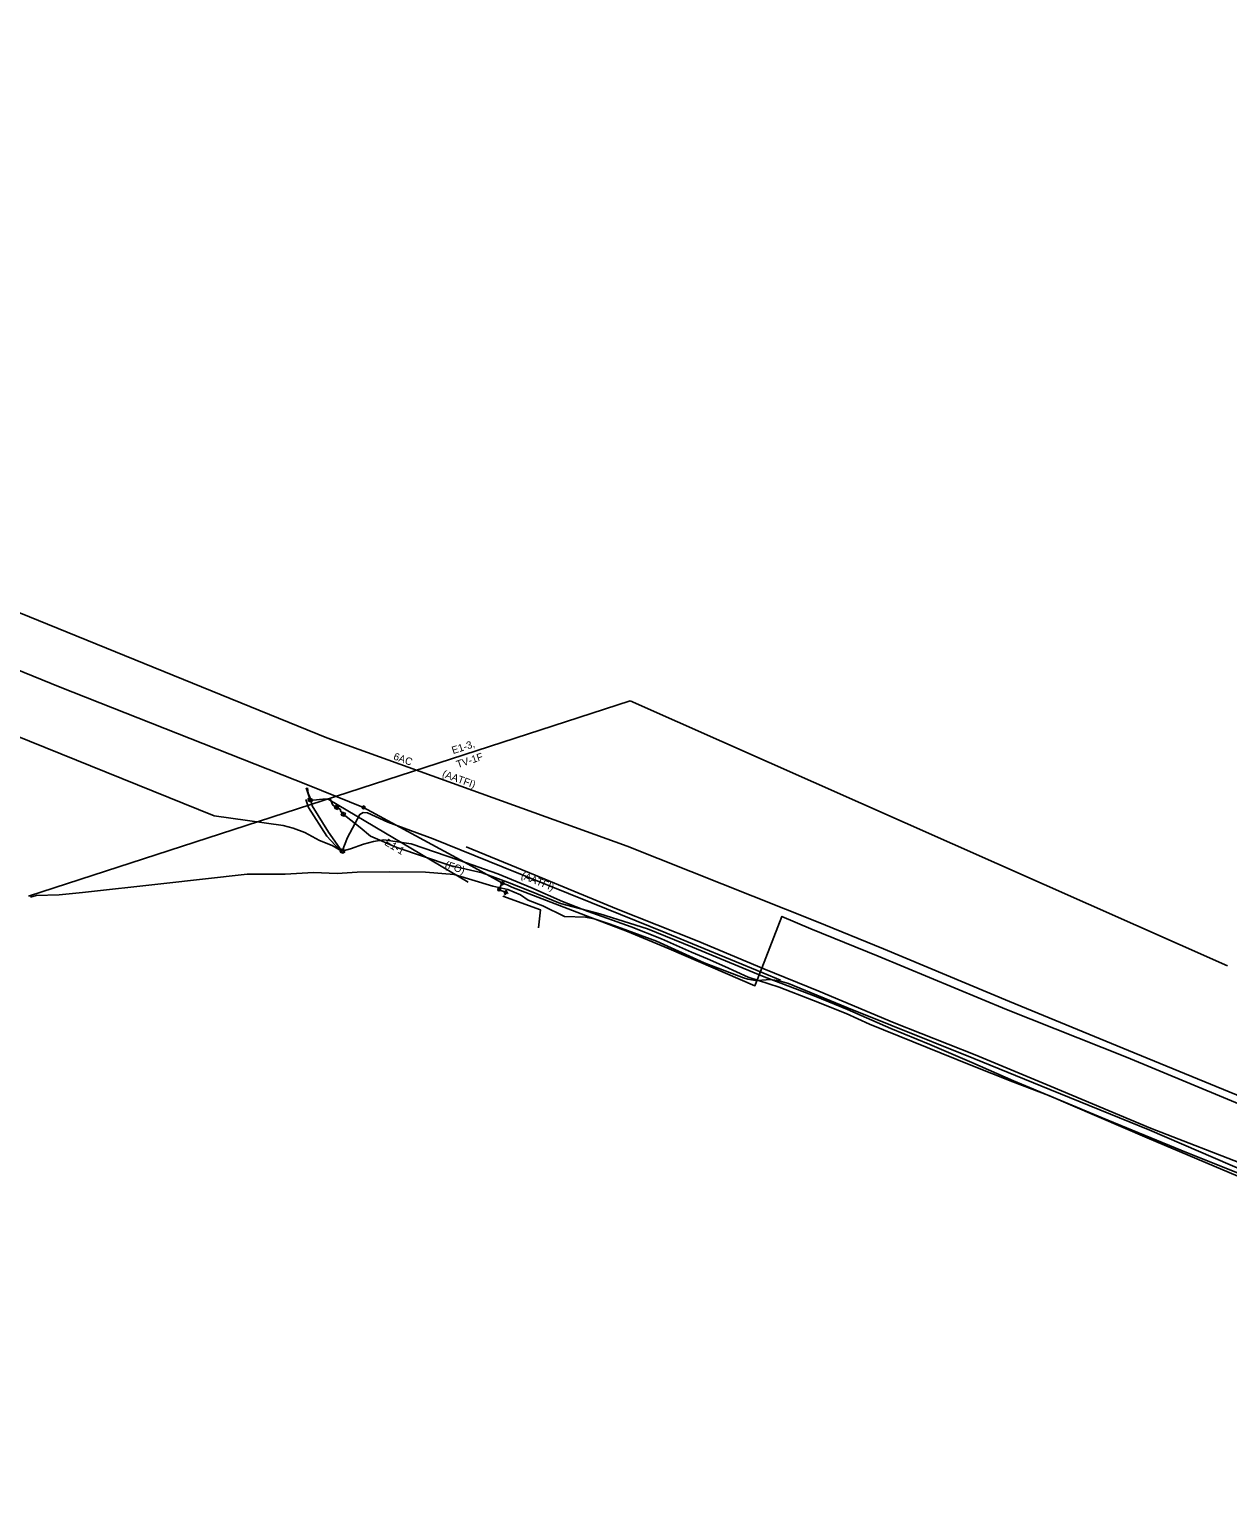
# Model space of a CAD drawing. Extents: x 2166631 to 2170707, y 207428 to 209111.
# Drawn here: x 2169640 to 2170250, y 207433 to 208185 of the extents above; entities that cross this region are included whole.
import ezdxf

# ---------------------------------------------------------------- set-up
doc = ezdxf.new("R2010")
doc.units = 0
for name, color, linetype in [('RD_EX_SU_Elec', 7, 'Continuous'), ('RD_EX_SU_H2O', 7, 'Continuous'), ('RD_EX_SU_Misc', 7, 'Continuous'), ('RD_EX_SU_Ovhd', 7, 'Continuous'), ('RD_EX_SU_Telecom', 7, 'Continuous'), ('RD_EX_SU_TX_H2O', 7, 'Continuous'), ('RD_EX_SU_TX_Ovhd', 7, 'Continuous'), ('RD_EX_SU_TX_Telecom', 7, 'Continuous'), ('RD_EX_UT', 7, 'Continuous')]:
    doc.layers.add(name, color=color, linetype=linetype)

msp = doc.modelspace()

# ---------------------------------------------------------------- linework, layer by layer
at = {"layer": 'RD_EX_SU_Elec'}
for p, q in [((2169782.23, 207792.66), (2169781.54, 207792.94)), ((2169783.6, 207792.1), (2169784.31, 207791.81))]:
    msp.add_line(p, q, dxfattribs=at)
msp.add_lwpolyline([(2169780.98, 207798.51), (2169782.91, 207792.38), (2169784.43, 207792.27), (2169789.41, 207792.82), (2169793.01, 207792.88)], dxfattribs=at)
msp.add_lwpolyline([(2169781.95, 207791.98), (2169783.32, 207791.42), (2169783.88, 207792.78), (2169782.51, 207793.34)], close=True, dxfattribs=at)
at = {"layer": 'RD_EX_SU_H2O'}
for p, q in [((2169882.14, 207744.71), (2169881.95, 207744.22)), ((2169881.95, 207744.22), (2169882.26, 207744.1)), ((2169882.26, 207744.1), (2169882.46, 207744.6)), ((2169882.81, 207746.41), (2169882.62, 207745.93)), ((2169883.12, 207746.28), (2169882.81, 207746.41)), ((2169882.93, 207745.8), (2169883.12, 207746.28)), ((2169883.05, 207744.86), (2169883.45, 207744.7)), ((2169883.58, 207745.01), (2169883.18, 207745.17)), ((2169883.45, 207744.7), (2169883.58, 207745.01))]:
    msp.add_line(p, q, dxfattribs=at)
for points in [[(2167150.83, 208898.91), (2167395.21, 208799.32), (2168738, 208252.12), (2168771.81, 208104.5), (2168930.48, 208039.81), (2169042.32, 208128.69), (2169791.43, 207823.92)], [(2167144.87, 208875.61), (2167820.52, 208600.61), (2168758.4, 208215.02), (2168781.36, 208111.79), (2168927.74, 208052.43), (2169006.44, 208114.13), (2169655.67, 207849.79), (2169781.62, 207799.98)], [(2169791.43, 207823.92), (2169944.38, 207768.79), (2170040.91, 207730.46)], [(2169781.62, 207799.98), (2169810.21, 207788.55), (2169863.45, 207759.58)], [(2169863.45, 207759.58), (2169880.88, 207749.91), (2169883.32, 207749.12), (2169885.67, 207747.99), (2169923.16, 207733.55), (2169944.55, 207725.32), (2169965.76, 207716.47), (2170009.51, 207697.71), (2170013.01, 207706.66)], [(2169880.87, 207749.92), (2169880.02, 207748.71), (2169879.2, 207746.78), (2169882.51, 207745.27)], [(2170013.01, 207706.66), (2170023.24, 207733.01), (2170037.97, 207726.7), (2170072.27, 207712.81), (2170137.67, 207685.67), (2170198.72, 207661.36), (2170282.49, 207626.65), (2170365.99, 207592.97), (2170429.01, 207568.39), (2170520.28, 207530.31), (2170608.27, 207494.22), (2170688.4, 207461.16)], [(2170040.91, 207730.46), (2170074.97, 207716.6), (2170139.12, 207689.74), (2170199.72, 207664.84), (2170283.36, 207630.46), (2170366.02, 207596.69), (2170430.49, 207571.75), (2170522, 207534.52), (2170609.98, 207499.23), (2170690.07, 207465.3)]]:
    msp.add_lwpolyline(points, dxfattribs=at)
for centre, radius in [((2169810.21, 207788.55), 0.719), ((2169880.88, 207749.91), 0.719), ((2169879.2, 207746.78), 0.719), ((2169882.51, 207745.27), 0.671), ((2169882.51, 207745.27), 0.0839)]:
    msp.add_circle(centre, radius, dxfattribs=at)
for start, end in [(236.19798, 265.1743), (51.85169, 80.82801), (322.75852, 351.72576)]:
    msp.add_arc((2169882.51, 207745.27), 0.671, start, end, dxfattribs=at)
at = {"layer": 'RD_EX_SU_Misc'}
for points in [[(2169862.5, 207768.4), (2169897.49, 207753.98), (2169938.99, 207736.93), (2169980.13, 207720.62), (2170014.07, 207706.31), (2170042.02, 207694.97), (2170080.51, 207678.79), (2170121.63, 207662.47)], [(2169881.08, 207743.33), (2169900.33, 207736.35), (2169899.26, 207727.22)], [(2170121.63, 207662.47), (2170160.32, 207646.4), (2170211.03, 207625.24), (2170261.83, 207605.45), (2170316.4, 207582.95), (2170396.84, 207550.58), (2170452.09, 207528.32), (2170527.35, 207497.45), (2170555.45, 207485.8), (2170606.13, 207465.24), (2170659.05, 207443.3), (2170677.97, 207435.37)]]:
    msp.add_lwpolyline(points, dxfattribs=at)
at = {"layer": 'RD_EX_SU_Ovhd'}
for p, q in [((2169639.53, 207743.4), (2169945.89, 207842.9)), ((2169945.89, 207842.9), (2169945.89, 207842.9)), ((2169945.89, 207842.9), (2170250.2, 207707.83))]:
    msp.add_line(p, q, dxfattribs=at)
at = {"layer": 'RD_EX_SU_Telecom'}
for p, q in [((2169798.58, 207766.56), (2169797.84, 207766.86)), ((2169799.94, 207767.74), (2169799.63, 207766.99)), ((2169800.82, 207765.64), (2169800.07, 207765.95))]:
    msp.add_line(p, q, dxfattribs=at)
for points in [[(2166965.96, 208941.15), (2166969.97, 208939.32), (2166972.54, 208937.72), (2166975.39, 208935.4), (2167008.01, 208918.47), (2167086.86, 208878.73), (2167173.38, 208840.74), (2167224.76, 208818.58), (2167737.21, 208591.61), (2169733.98, 207784.3), (2169769.15, 207779.36)], [(2169783.18, 207792.88), (2169781.89, 207795.74), (2169781.52, 207798.52)], [(2169799.13, 207766.26), (2169795.65, 207769.36), (2169791.52, 207773.85), (2169782.08, 207788.54), (2169781.55, 207789.95), (2169780.82, 207792.51)], [(2169799.13, 207766.26), (2169792.28, 207776.02), (2169783.97, 207789.39), (2169783.18, 207792.88)], [(2169793.1, 207792.93), (2169794.56, 207789.69), (2169796.41, 207788.54), (2169798.2, 207787.61), (2169798.57, 207786.42), (2169799.84, 207785.07), (2169801.25, 207783.98), (2169808.41, 207778.26), (2169813.75, 207773.88), (2169827.02, 207768.07), (2169854.29, 207758.89), (2169870.52, 207755.17), (2169883.46, 207750.55), (2169894.65, 207746.11), (2169910.54, 207739.68), (2169930.55, 207734.31), (2169954.74, 207726.77), (2169977.73, 207717.39), (2169977.7, 207717.42), (2170013.39, 207702.67), (2170040.58, 207692.34), (2170056.62, 207685.7), (2170078.7, 207675.95), (2170098.6, 207667.89), (2170119.95, 207658.72), (2170141.28, 207649.27), (2170186.44, 207630.53), (2170226.52, 207614.03), (2170260.81, 207600.23)], [(2169799.33, 207766.25), (2169801.95, 207773.17), (2169808.34, 207784.95), (2169809.99, 207785.87), (2169812.21, 207785.73), (2169822.53, 207781.02), (2169845.61, 207772.49), (2169881.19, 207758.11), (2169925.86, 207740.1), (2169964.1, 207724.6), (2170013.46, 207704.31), (2170022.5, 207700.58)], [(2169769.15, 207779.36), (2169774.35, 207778), (2169780.32, 207775.72), (2169787.65, 207771.75), (2169794.13, 207769.11), (2169799.13, 207766.26), (2169803.45, 207767.49), (2169810.09, 207769.76), (2169815.19, 207771.19), (2169820.49, 207772.11), (2169834.47, 207769.98), (2169858.72, 207761.6), (2169878.62, 207754.64), (2169895.3, 207747.8), (2169911.53, 207740.69), (2169924.64, 207735.5), (2169946.41, 207727.79), (2169961.99, 207721.67), (2169977.12, 207714.79), (2169985.41, 207711.52), (2169994.16, 207707.57), (2170006.14, 207702.18), (2170021.83, 207696.99), (2170039.3, 207690.15), (2170056, 207683.57), (2170067.81, 207678.19), (2170119.45, 207657.28), (2170140.81, 207648.85), (2170159.28, 207641.79), (2170209.34, 207620.24), (2170259.93, 207598.85)], [(2169640.5, 207742.83), (2169643.37, 207743.73), (2169655.13, 207744.06), (2169667.03, 207745.21), (2169706.92, 207749.63), (2169750.94, 207754.52), (2169770.24, 207754.57), (2169784.66, 207755.32), (2169796.79, 207754.83), (2169806.96, 207755.65), (2169823.31, 207755.76), (2169841.73, 207755.63), (2169856.29, 207754.31), (2169875.95, 207748.47), (2169883.68, 207746.73), (2169890.06, 207743.96), (2169893.96, 207741.36), (2169901.46, 207738.41), (2169912.47, 207732.99), (2169923.18, 207732.73), (2169927.62, 207731.76), (2169935.78, 207729.04), (2169944.56, 207725.79), (2169959.43, 207720.41), (2169983.71, 207709.43), (2170003.76, 207701.81), (2170005.88, 207701.03), (2170009.56, 207700.47), (2170013.01, 207700.5), (2170017.43, 207700.86), (2170021.89, 207700.26), (2170026.55, 207698.81), (2170056.32, 207686.6), (2170078.73, 207677.66), (2170121.06, 207660.61)], [(2170121.06, 207660.61), (2170159.64, 207644.85), (2170210.64, 207624.19), (2170260.22, 207602.77), (2170315.77, 207581.03), (2170396.06, 207548.37), (2170450.46, 207525.69), (2170518.96, 207498.35), (2170519.2, 207498.21), (2170531.22, 207493.08), (2170538.54, 207490.18), (2170554.58, 207483.06), (2170604.4, 207463), (2170658.1, 207440.56), (2170676.84, 207432.57)]]:
    msp.add_lwpolyline(points, dxfattribs=at)
for points in [[(2169795.37, 207788.09), (2169796.86, 207787.5), (2169797.45, 207788.99), (2169795.95, 207789.58)], [(2169798.8, 207784.62), (2169800.29, 207784.02), (2169800.89, 207785.51), (2169799.4, 207786.11)], [(2169798.28, 207765.81), (2169799.76, 207765.2), (2169800.38, 207766.69), (2169798.89, 207767.3)]]:
    msp.add_lwpolyline(points, close=True, dxfattribs=at)
at = {"layer": 'RD_EX_UT'}
msp.add_line((2169792.21, 207792.69), (2169863.45, 207750.43), dxfattribs=at)

# ---------------------------------------------------------------- texts
at = {"layer": 'RD_EX_SU_Elec'}
msp.add_text('e', height=1.28, rotation=337.72655, dxfattribs=at).set_placement((2169782.34, 207792.15))
at = {"layer": 'RD_EX_SU_H2O'}
for p in [(2169809.79, 207788.03), (2169880.46, 207749.39), (2169878.78, 207746.26)]:
    msp.add_text('v', height=1.28, dxfattribs=at).set_placement(p)
at = {"layer": 'RD_EX_SU_Telecom'}
for s, height, rotation, p in [('tv', 1.279, 338.51762, (2169795.58, 207788.22)), ('tv', 1.279, 338.11207, (2169799.02, 207784.76)), ('t', 1.28, 337.64183, (2169798.84, 207765.81))]:
    msp.add_text(s, height=height, rotation=rotation, dxfattribs=at).set_placement(p)
at = {"layer": 'RD_EX_SU_TX_H2O'}
for s, p in [('6AC', (2169825.06, 207813.06)), ('(AATFI)', (2169849.89, 207804.2))]:
    msp.add_text(s, height=3.75, rotation=340.17795, dxfattribs=at).set_placement(p)
at = {"layer": 'RD_EX_SU_TX_Ovhd'}
for s, rotation, p in [('E1-3,', 18.09314, (2169855.79, 207815.68)), ('TV-1F', 18.09314, (2169858.12, 207808.55)), ('E1-1', 329.32332, (2169820.47, 207769.67))]:
    msp.add_text(s, height=3.75, rotation=rotation, dxfattribs=at).set_placement(p)
at = {"layer": 'RD_EX_SU_TX_Telecom'}
for s, rotation, p in [('(FO)', 341.38841, (2169851.28, 207757.92)), ('(AATFI)', 338.04369, (2169890.04, 207752.52))]:
    msp.add_text(s, height=3.75, rotation=rotation, dxfattribs=at).set_placement(p)

doc.saveas('drawing.dxf')
